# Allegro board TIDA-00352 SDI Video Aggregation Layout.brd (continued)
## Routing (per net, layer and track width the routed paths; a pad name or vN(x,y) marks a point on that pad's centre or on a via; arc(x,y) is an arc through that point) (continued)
GND_CAGE: length 4.8
  L3_SIG2 w1.016: J73.40 J73.39
  vias: v1(20.5,26.95) v1(20.5,26.44) v1(21.01,26.95) v1(21.01,26.44) v1(21.49,26.95) v1(21.49,26.44) v1(26.85,42.01) v1(26.85,41.5) v1(27.33,42.01) v1(27.33,41.5) v1(27.81,42.01) v1(27.81,41.5)
VCC_PRI: length 3
  L3_SIG2 w0.152: v1(11.08,161.18) 11.08,161.61 11.11,161.64 v1(11.11,162.89)
  BOTTOM w0.254: C690.1 9.31,161.06 R776.1
VCC_SEC: length 3
  TOP w0.254: v1(12.55,136) 12.55,135.52 12.51,135.49 v1(12.51,134.29)
  BOTTOM w0.254: R792.1 14.31,136.12 C695.1
VDDA: length 68.9
  TOP w0.254: J100.27 v1(96.59,99.87)
  TOP w1.016: v1(105.92,32.26) 104.27,33.91 C86.1 C85.1 v1(101.35,36.45) v1(101.35,36.96)
  L3_SIG2 w0.152: v1(64.18,98.77) 82.12,98.77 84.52,101.17 91.88,101.17 92.34,100.71 95.75,100.71 v1(96.59,99.87)
  L14_SIG3 w0.152: v1(64.18,73.91) 64.48,74.21 64.48,74.26 64.82,74.6 64.82,77.04 64.18,77.68 v1(64.18,98.77)
  vias: v1(77.22,31.88) v1(97.16,32) v1(100.84,37.47) v1(100.84,36.96) v1(100.84,36.45) v1(101.35,37.47) v1(101.85,37.47) v1(101.85,36.96) v1(101.85,36.45) v1(105.41,32.26) v1(106.43,32.26) v2(41.09,73.16) v2(42.09,74.16) v2(50.09,76.16) v2(50.09,74.16) v2(50.09,73.16) v2(50.09,71.16)
VDDD: length 25.3
  TOP w0.254: J100.31 v1(98.59,99.87)
  TOP w1.016: v1(105.41,87) v1(104.9,87) C109.1 C110.1 102.36,84.07 v1(100.71,82.42)
  L14_SIG3 w0.152: v1(105.92,87.5) 105.92,90.55 100.33,96.14 100.33,98.13 v1(98.59,99.87)
  BOTTOM w0.254: C164.1 46.14,75.16 v2(46.09,75.16)
  vias: v1(52.1,65.32) v1(100.71,82.93) v1(100.71,81.92) v1(104.9,87.5) v1(104.9,86.49) v1(105.41,87.5) v1(105.41,86.49) v1(105.92,87) v1(105.92,86.49) v2(44.09,75.16) v2(44.09,72.16) v2(46.09,73.16) v2(46.09,72.16)
VDDO: length 12.3
  TOP w0.254: v1(83.94,23.17) v1(83.31,23.17) ; J100.35 v1(100.59,99.87)
  TOP w1.016: v1(65.41,133.6) 63.75,135.25 C129.1 C128.1 v1(60.83,137.92) v1(60.83,138.43)
  BOTTOM w0.254: R305.2 v1(32.92,9.14) ; U43.2 v1(25.44,7.87)
  vias: v1(23.51,8.04) v1(24.71,13.26) v1(28,13.26) v1(30.45,73.7) v1(55.54,15.25) v1(55.54,14.61) v1(55.54,13.98) v1(55.69,11.74) v1(55.75,12.83) v1(60.07,13.54) v1(60.33,138.94) v1(60.33,138.43) v1(60.33,137.92) v1(60.83,138.94) v1(61.34,138.94) v1(61.34,138.43) v1(61.34,137.92) v1(64.9,133.6) v1(65.91,133.6) v1(66.17,13.46) v1(67.44,13.46) v1(68.71,13.46) v1(69.98,13.46) v1(74.04,13.46) v1(74.45,102.29) v1(74.45,101.78) v1(74.83,100.89) v1(76,102.12) v1(77.09,103.38) v1(81.66,7.37) v1(82.67,23.17) v1(84.2,7.37) v1(105.66,11.3) v1(106.93,11.3) v1(108.2,11.3) v1(109.47,11.3) v1(110.74,11.3) v1(112.01,11.18) v1(113.28,11.05) v1(114.43,19) v1(115.07,19) v1(115.7,19) v1(118.49,25.53) v1(121.67,18.54) v1(123.06,18.54) v2(45.09,77.16) v2(45.09,70.16)
VDDRA_HS: length 66.4
  TOP w0.254: J100.39 v1(102.59,99.87)
  TOP w1.016: v1(73.03,133.6) 71.37,135.25 C100.1 C99.1 v1(68.45,137.92) v1(68.45,138.43)
  L3_SIG2 w0.152: v1(102.59,99.87) 102.59,102.51 100.08,105.03 95.76,105.03 93.98,106.81 93.98,113.16 91.19,115.95 91.19,130.3 89.92,131.57 75.56,131.57 v1(73.53,133.6)
  vias: v1(67.94,138.94) v1(67.94,138.43) v1(67.94,137.92) v1(68.45,138.94) v1(68.96,138.94) v1(68.96,138.43) v1(68.96,137.92) v1(72.52,133.6) v2(41.09,72.16)
VDDRA_LS: length 9.6
  TOP w0.254: J100.37 v1(101.59,97.28)
  TOP w1.016: v1(97.16,133.73) 95.5,135.38 C90.1 C89.1 v1(92.58,137.92) v1(92.58,138.43)
  vias: v1(92.08,138.94) v1(92.08,138.43) v1(92.08,137.92) v1(92.58,138.94) v1(93.09,138.94) v1(93.09,138.43) v1(93.09,137.92) v1(96.65,133.73) v1(97.66,133.73) v2(49.09,70.16)
VDDRB_HS: length 61.2
  TOP w0.254: J100.43 v1(104.59,99.87)
  TOP w1.016: v1(80.77,133.6) 79.12,135.25 C124.1 C123.1 v1(76.2,137.92) v1(76.2,138.43)
  L3_SIG2 w0.152: v1(104.59,99.87) 104.59,104.58 102.74,106.43 98.42,106.43 95.34,109.51 95.34,114.21 92.25,117.3 92.25,131.41 89.5,134.16 81.84,134.16 v1(81.28,133.6)
  vias: v1(75.69,138.94) v1(75.69,138.43) v1(75.69,137.92) v1(76.2,138.94) v1(76.71,138.94) v1(76.71,138.43) v1(76.71,137.92) v1(80.26,133.6) v2(41.09,76.16)
VDDRB_LS: length 54.8
  TOP w0.254: J100.41 v1(103.59,97.28)
  TOP w1.016: v1(88.77,133.73) 87.12,135.38 C114.1 C113.1 v1(84.2,137.92) v1(84.2,138.43)
  L3_SIG2 w0.152: v1(103.59,97.28) 103.59,102.91 103.05,103.45 103.05,104.47 101.73,105.79 96.9,105.79 95.76,106.93 95.76,108.3 94.49,109.57 94.49,113.68 91.8,116.37 91.8,131.22 v1(89.28,133.73)
  vias: v1(83.69,138.94) v1(83.69,138.43) v1(83.69,137.92) v1(84.2,138.94) v1(84.71,138.94) v1(84.71,138.43) v1(84.71,137.92) v1(88.27,133.73) v2(49.09,77.16)
VDDT: length 60.7
  TOP w0.254: J100.29 v1(97.59,97.28)
  TOP w1.016: v1(118.11,132.46) 116.84,131.19 C95.1 C94.1 v1(113.92,127.89) v1(113.41,127.89)
  L3_SIG2 w0.152: v1(112.9,127.38) 111,127.38 109.22,125.6 109.22,115.32 108.58,114.68 108.58,107.57 110.36,105.79 110.36,104.78 112.05,103.09 112.05,97.09 109.95,95 99.88,95 v1(97.59,97.28)
  vias: v1(64.11,75.06) v1(112.9,128.4) v1(112.9,127.89) v1(113.41,128.4) v1(113.41,127.38) v1(113.92,128.4) v1(113.92,127.38) v1(118.11,132.97) v1(118.11,131.95) v2(43.09,73.16) v2(48.09,74.16) v2(48.09,73.16)
1P0V_A1: length 76
  TOP w0.254: J100.9 v1(87.59,99.87)
  TOP w1.016: v1(101.35,39.65) v1(101.35,40.28) 101.35,43.69 100.33,44.7 91.06,44.7 90.22,43.87 v1(90.22,43.18)
  L14_SIG3 w0.152: v1(87.59,99.87) 90.16,97.3 90.16,68.57 90.6,68.12 90.6,58.88 90.22,58.49 v1(90.22,43.18)
  vias: v1(90.2,42.55) v1(90.2,41.86) v1(90.2,41.22) v1(90.83,42.55) v1(90.83,41.86) v1(90.83,41.22) v1(90.86,43.18) v1(91.21,39.38) v1(100.71,40.31) v1(100.71,39.67) v1(102.03,40.28) v1(102.03,39.65)
1P0V_A1_REG_ADJ: length 0.9
  BOTTOM w0.381: R50.2 v1(93.81,39.38)
1P0V_A1_REG_EN: length 123.4
  TOP w0.254: SW17.1 v1(109.73,132.45)
  L3_SIG2 w0.152: v1(95.25,47.37) 95.94,46.69 95.94,37.01 95.41,36.48 v1(95.41,35.17)
  L14_SIG3 w0.152: v1(95.25,47.37) 95.25,58.44 95.68,58.88 95.68,68.12 95.25,68.56 95.25,81.15 94.36,82.04 94.36,98.3 95.02,98.96 95.02,106.96 95.76,107.7 114.43,107.7 115.75,109.02 115.75,129.24 112.54,132.45 v1(109.73,132.45)
1P0V_A1_REG_SS:
  vias: v1(95.41,37.77)
1P0V_A1_REG_TRIM: length 1
  BOTTOM w0.254: R600.2 95.5,39.39 R52.1
1P0V_A2: length 61.7
  TOP w0.254: J100.11 v1(88.59,97.28)
  L3_SIG2 w0.152: v1(110.01,122.38) 109.83,122.2 109.83,108.61 113.31,105.13 113.31,96.4 110.74,93.83 95.15,93.83 91.26,97.71 90.41,97.71 89.98,97.28 v1(88.59,97.28)
  BOTTOM w1.016: C605.1 110.24,124.08 110.31,124.16 L3.1
  vias: v1(110.03,124.33) v1(110.01,123.7) v1(110.01,123.01) v1(110.64,123.7) v1(110.64,123.01) v1(110.64,122.38) v1(110.67,124.33) v1(111.02,120.53)
1P0V_A2_REG_ADJ: length 0.9
  BOTTOM w0.381: R603.2 v1(113.62,120.53)
1P0V_A2_REG_EN: length 23.4
  TOP w0.254: SW17.3 v1(108.46,132.45)
  L3_SIG2 w0.152: v1(115.22,116.33) 115.82,116.93 115.82,129.16 111.85,133.13 109.14,133.13 v1(108.46,132.45)
1P0V_A2_REG_SS:
  vias: v1(115.22,118.93)
1P0V_A2_REG_TRIM: length 1
  BOTTOM w0.381: R604.1 115.3,121.5 R605.2
1P0V_D1: length 39.4
  TOP w0.254: J100.13 v1(89.59,99.87)
  L3_SIG2 w0.152: v1(89.59,99.87) 87.76,98.04 87.76,95.63 90.93,92.46 107.24,92.46 v1(112.7,87)
  BOTTOM w1.016: C27.1 110.32,87.38 109.94,87 L5.1
  vias: v1(112.67,86.36) v1(112.67,85.67) v1(112.67,85.04) v1(113.33,87) v1(113.31,86.36) v1(113.31,85.67) v1(113.31,85.04) v1(113.69,83.19)
1P0V_D1_REG_ADJ: length 0.9
  BOTTOM w0.381: R67.2 v1(116.29,83.19)
1P0V_D1_REG_EN: length 65.3
  TOP w0.254: SW17.5 v1(107.19,132.45)
  L3_SIG2 w0.152: v1(117.89,78.99) 117.22,79.66 117.22,103.38 117.98,104.14 117.98,104.52 119.51,106.05 119.51,124.94 116.33,128.12 116.33,129.41 112.14,133.6 108.97,133.6 108.95,133.59 108.33,133.59 v1(107.19,132.45)
1P0V_D1_REG_SS:
  vias: v1(117.89,81.59)
1P0V_D1_REG_TRIM: length 1
  BOTTOM w0.381: R601.2 117.97,84.16 R69.1
1P0V_D2: length 77.2
  TOP w0.254: J100.15 v1(90.59,97.28)
  L3_SIG2 w0.152: v1(110.67,92.91) 94.96,92.91 v1(90.59,97.28)
  L14_SIG3 w0.152: v1(110.67,92.91) 110.67,83.01 111.63,82.04 111.63,78.49 111.3,78.16 v1(111.3,43.43)
  BOTTOM w1.016: L7.1 110.95,45.77 110.87,45.69 C613.1
  vias: v1(110.64,42.8) v1(110.64,42.11) v1(110.64,41.48) v1(110.67,43.43) v1(111.28,42.8) v1(111.28,42.11) v1(111.28,41.48) v1(111.66,39.63)
1P0V_D2_REG_ADJ: length 0.9
  BOTTOM w0.381: R607.2 v1(114.26,39.63)
1P0V_D2_REG_EN: length 116.8
  TOP w0.254: SW17.7 v1(105.92,132.45)
  L3_SIG2 w0.152: v1(115.86,35.43) 116.58,35.43 123.27,42.11 123.27,59.61 122.89,59.99 122.89,65.74 123.27,66.12 123.27,76.63 118.87,81.03 118.87,85.98 117.97,86.88 117.97,103.11 120.02,105.16 120.02,125.48 116.84,128.65 116.84,129.67 112.39,134.11 108.2,134.11 108.14,134.05 107.52,134.05 v1(105.92,132.45)
1P0V_D2_REG_SS:
  vias: v1(115.86,38.03)
1P0V_D2_REG_TRIM: length 1
  BOTTOM w0.381: R609.2 115.94,40.6 R608.1
1P5V: length 64.1
  TOP w0.254: J100.17 v1(91.59,99.87)
  L14_SIG3 w0.152: v1(91.59,99.87) 91.59,100.69 89.28,103 89.28,105.66 88.39,106.55 88.39,130.56 87.76,131.19 87.76,144.4 88.14,144.78 88.14,148.21 90.3,150.37 92,150.37 v1(92.96,151.33)
  BOTTOM w1.016: v1(92.33,151.99) 92.33,155.96 91.44,156.84 JMP35.1
  vias: v1(89.16,150.98) v1(91.01,151.99) v1(91.01,151.36) v1(91.64,151.99) v1(91.64,151.36) v1(92.33,151.36) v1(92.96,151.97)
1P5V_REG_EN: length 29.9
  TOP w0.254: SW17.9 v1(104.65,132.45)
  L3_SIG2 w0.152: v1(104.65,132.45) 104.65,134.49 103.81,135.33 103.81,138.24 100.07,141.99 89.15,141.99 84.96,146.18 v1(84.96,146.78)
1P5V_REG_EN_ADJ: length 1
  BOTTOM w0.254: R84.2 v1(89.16,148.29)
1P5V_REG_SS:
  vias: v1(87.56,146.78)
1P5V_REG_TRIM: length 1.4
  BOTTOM w0.254: v1(90.53,146.56) 89.21,146.56 R86.2
1P8_VREG_SS:
  vias: v1(68.51,146.78)
1P8V: length 87.4
  TOP w0.254: J100.19 v1(92.59,97.28)
  L14_SIG3 w0.152: JMP35.3 84.33,156.21 84.33,152.65 82.93,151.25 82.93,133.23 86.36,129.79 86.36,106.93 87.5,105.79 87.5,103.25 89.03,101.73 89.03,99.44 90.75,97.71 90.77,97.71 91.2,97.28 v1(92.59,97.28)
  BOTTOM w1.016: v1(73.28,151.99) 73.28,155.96 76.71,159.38 85.22,159.38 JMP35.3
  vias: v1(70.11,150.98) v1(71.96,151.99) v1(71.96,151.36) v1(72.59,151.99) v1(72.59,151.36) v1(73.28,151.36) v1(73.91,151.97) v1(73.91,151.33)
1P8V_REG_ADJ: length 0.9
  BOTTOM w0.381: R118.2 v1(70.11,148.38)
1P8V_REG_EN: length 47.3
  TOP w0.254: SW17.11 v1(103.38,132.45)
  L3_SIG2 w0.152: v1(103.38,132.45) 103.38,134.37 102.74,135 102.74,138.05 99.44,141.35 87.76,141.35 87,142.11 70.57,142.11 v1(65.91,146.78)
1P8V_REG_TRIM: length 1
  BOTTOM w0.381: R120.1 71.08,146.7 R613.2
2P5V: length 189.2
  TOP w0.254: J100.23 v1(94.59,99.87)
  L3_SIG2 w0.152: v1(14.48,43.56) 14.48,82.17 18.92,86.61 v1(65.28,86.61) ; v1(17.27,43.56) v1(24.51,43.56) ; v1(94.59,99.87) 92.53,99.87 91.69,100.71 84.71,100.71 79.88,95.89 v1(66.17,95.89)
  L14_SIG3 w0.152: v1(65.28,86.61) 66.17,87.5 v1(66.17,95.89) ; v1(37.79,15.3) 37.79,17.97 33.78,21.97 33.78,24.05 28.62,29.21 26.42,29.21 24,31.62 24,43.05 v1(24.51,43.56) ; v1(14.48,43.56) v1(17.27,43.56)
  BOTTOM w0.305: C615.1 37.79,15.3 v1(37.79,15.3)
  BOTTOM w0.635: R616.1 38.67,11.87 v1(37.79,11.87)
  BOTTOM w1.016: JMP77.3 37.72,9.4 37.79,9.46 v1(37.79,11.87) v1(37.79,15.3) U103.5
2P5V_EN: length 3.3
  TOP w0.254: v1(39.68,20.95) 39.08,21.56 39.08,21.76 v1(38.73,22.1)
  BOTTOM w0.254: U103.3 v1(39.68,20.95)
2P5V_LED: length 1.9
  BOTTOM w0.508: R616.2 39.94,11.87 v1(41.78,11.87)
3P3V: length 14
  TOP w0.254: v1(96.72,22.27) 96.88,22.1 U42.27 ; U42.31 v1(96.92,20.1) ; J100.25 v1(95.59,97.28)
  L5_PWR w0.381: 36.84,3.3 JMP77.1 ; JMP77.1 37.72,4.18 ; JMP77.1 37.72,2.43 ; JMP77.1 38.6,3.3 ; JMP62.1 62.99,15.3 ; JMP62.1 62.99,13.55 ; JMP62.1 63.87,14.43 ; JMP62.1 62.12,14.43
  BOTTOM w0.254: v1(93.85,20.32) 94.23,20.32 94.3,20.39 R477.1 ; v1(93.98,22.1) 94.02,22.06 R472.1 ; C298.1 v1(50.49,33.46) ; v1(96.72,22.27) 97.28,22.27 C280.1
  vias: v1(2.16,22.86) v1(7.11,167.96) v1(10.22,167.94) v1(11.55,133.59) v1(12.08,163.59) v1(12.45,167.94) v1(13.53,129.24) v1(13.49,24.64) v1(13.72,21.84) v1(15.11,7.11) v1(16.13,21.34) v1(22.62,20.99) v1(30.51,23.24) v1(32.09,32.73) v1(32.13,31.11) v1(39.68,22.1) v1(44.8,36.37) v1(44.8,26.34) v1(46.7,36.37) v1(46.7,26.34) v1(49.66,39.37) v1(49.78,41.91) v1(50.98,40.13) v1(50.98,39.5) v1(51.74,40.13) v1(51.77,39.5) v1(52.76,40.13) v1(52.76,39.5) v1(53.34,25.81) v1(54.34,20.74) v1(54.36,22.48) v1(54.48,42.67) v1(54.48,41.73) v1(54.48,40.89) v1(54.48,39.5) v1(54.48,38.68) v1(54.48,37.72) v1(73.15,112.14) v1(74.45,103.89) v1(75.13,106.03) v1(75.18,40.51) v1(78.74,107.57) v1(79.12,106.28) v1(79.12,105.27) v1(80.77,111.12) v1(87.12,40.51) v1(88.27,23.17) v1(88.91,23.17) v1(89.54,23.17) v1(94.36,23.5) v1(94.67,21.22) v1(94.67,19.55) v1(96.82,124.33) v1(96.8,123.7) v1(96.8,123.01) v1(96.8,122.38) v1(97.43,123.7) v1(97.43,123.01) v1(97.43,122.38) v1(97.46,124.33) v1(97.82,120.53) v1(108.83,19) v1(109.47,19) v1(110.1,19)
3P3V_C_REG_ADJ: length 0.9
  BOTTOM w0.381: R186.2 v1(66.25,168.79)
3P3V_C_REG_SS:
  vias: v1(67.85,167.19)
3P3V_CLK: length 78
  TOP w0.254: J100.45 v1(105.59,97.28)
  TOP w1.016: 62.87,172.4 C74.1
  L3_SIG2 w0.152: v1(66.67,86.49) 95.63,86.49 98.42,89.28 v1(107.19,89.28)
  L14_SIG3 w0.152: v1(107.19,89.28) 107.19,95.68 v1(105.59,97.28) ; v1(66.67,86.49) 66.67,103.76 62.56,107.88 v1(62.56,110.44)
  vias: v1(31.36,110.97) v1(33.02,111.77) v1(32.96,110.82) v1(45.45,110.72) v1(47.12,111.52) v1(47.06,110.57) v1(55.96,113.76) v1(56.03,112.23) v1(56.24,172.34) v1(56.24,165.74) v1(56.26,173.61) v1(56.26,172.97) v1(56.26,167) v1(56.26,166.37) v1(56.29,139.19) v1(56.29,138.56) v1(56.26,137.92) v1(56.41,160.4) v1(56.41,159.77) v1(56.39,159.13) v1(56.41,153.54) v1(56.41,152.91) v1(56.39,152.27) v1(56.41,146.05) v1(56.41,145.41) v1(56.39,144.78) v1(56.64,130.81) v1(56.67,132.08) v1(56.67,131.44) v1(56.85,173.61) v1(56.85,172.97) v1(56.82,172.34) v1(56.95,167) v1(56.95,166.37) v1(56.92,165.74) v1(56.95,137.92) v1(56.97,139.19) v1(56.97,138.56) v1(57.1,160.4) v1(57.1,159.77) v1(57.07,159.13) v1(57.1,153.54) v1(57.1,152.91) v1(57.07,152.27) v1(57.1,146.05) v1(57.1,145.41) v1(57.07,144.78) v1(57.07,119.36) v1(57.33,130.81) v1(57.35,132.08) v1(57.35,131.44) v1(58.18,119.41) v1(62.64,171.96) v1(62.64,171.27) v1(62.64,170.64) v1(62.61,111.39) v1(62.66,172.59) v1(63.3,172.59) v1(63.27,171.96) v1(63.27,171.27) v1(63.27,170.64) v1(63.65,168.79) v1(73.15,163.58) v1(73.15,161.16) v1(73.28,168.4) v1(73.28,165.99)
3P3V_CLK_REG_EN: length 64.7
  TOP w0.254: SW17.15 v1(100.84,132.45)
  L3_SIG2 w0.152: v1(67.85,164.59) 66.92,164.59 65.48,163.14 65.48,147.01 65.41,146.94 65.41,146.56 65.48,146.49 65.48,146.14 70.01,141.6 86.61,141.6 88.01,140.21 97.66,140.21 100.84,137.03 v1(100.84,132.45)
3P3V_CLK_REG_TRIM: length 1
  BOTTOM w0.381: R610.2 67.93,169.76 R188.1
3P3V_REG_EN: length 17.7
  TOP w0.254: SW17.13 v1(102.11,132.45)
  L3_SIG2 w0.152: v1(102.02,116.33) 102.74,117.05 102.74,130.3 102.11,130.94 v1(102.11,132.45)
3P3V_REG_TRIM: length 1
  BOTTOM w0.254: R171.1 102.09,121.5 R611.2
3P3V_RX:
  vias: v1(36.6,33.93) v1(37.23,33.93) v1(37.87,33.93) v1(46.7,27.86) v1(57.53,39.62) v1(57.53,38.68) v1(57.53,37.85) v1(59.18,37.26) v1(59.31,38.99)
3P3V_TX:
  vias: v1(36.6,34.73) v1(37.23,34.73) v1(37.87,34.73) v1(44.8,27.86) v1(46.7,15.61) v1(52.38,36) v1(57.53,42.67) v1(57.53,41.73) v1(57.53,40.89) v1(59.18,42.98) v1(59.31,41.27)
3P3V_USB: length 5
  TOP w0.254: J101.2 v1(12.98,10.67)
  BOTTOM w0.254: v1(12.98,10.67) 13.41,10.23 R639.2
3P3VREG_ADJ: length 0.9
  BOTTOM w0.254: R169.2 v1(100.42,120.53)
3P3VREG_SS:
  vias: v1(102.02,118.93)
/STATUS1: length 3.7
  BOTTOM w0.254: R708.2 R707.2 21.87,106.54 21.95,106.46 Q106.3
/STATUS1_B: length 1.3
  BOTTOM w0.254: R708.1 U106.6
A4N: length 25.5
  BOTTOM w0.114: C225.1 74.39,72.5 74.39,73.05 71.69,75.76 51.5,75.76 v2(51.09,76.16)
A4P: length 25.5
  BOTTOM w0.114: v2(51.09,75.16) 51.5,75.57 71.61,75.57 72.21,74.96 72.21,74.78 72.44,74.55 72.62,74.55 72.86,74.32 72.86,74.14 73.09,73.9 73.27,73.9 73.5,73.67 73.5,73.49 73.73,73.26 73.92,73.26 74.2,72.97 74.2,72.5 C223.1
A5N: length 38.6
  BOTTOM w0.114: v2(50.09,78.16) 50.09,78.13 50.46,77.75 81.63,77.75 84.54,74.84 84.54,72.51 C221.1
A5P: length 38.6
  BOTTOM w0.114: C219.1 84.35,72.49 84.35,72.73 84.16,72.93 84.16,73.19 84.35,73.38 84.35,73.65 84.16,73.84 84.16,74.1 84.35,74.3 84.35,74.76 81.55,77.56 50.46,77.56 50.09,77.2 v2(50.09,77.16)
A6N: length 53
  BOTTOM w0.114: v2(51.09,79.16) 51.5,78.76 95.61,78.76 99.79,74.58 99.79,72.5 C217.1
A6P: length 53.1
  BOTTOM w0.114: C215.1 99.6,72.5 99.6,74.5 99.43,74.67 99.24,74.67 99.01,74.9 99.01,75.09 98.78,75.32 98.6,75.32 98.37,75.55 98.37,75.74 98.13,75.97 97.95,75.97 97.72,76.2 97.72,76.38 95.54,78.57 51.5,78.57 v2(51.09,78.16)
A7N: length 67.5
  BOTTOM w0.114: C213.1 109.95,72.5 109.95,74.33 103.8,80.47 48.81,80.47 48.5,80.17 48.5,79.68 48.5,79.56 v2(48.09,79.16)
A7P: length 67.5
  BOTTOM w0.114: v2(49.09,79.16) 48.69,79.56 48.69,79.57 48.69,80.09 48.89,80.28 103.72,80.28 107.14,76.86 107.14,76.79 107.14,76.6 107.33,76.41 107.41,76.41 107.6,76.41 107.79,76.22 107.79,76.14 107.79,75.95 107.98,75.76 108.06,75.76 108.25,75.76 108.44,75.57 108.44,75.49 108.44,75.3 108.63,75.11 108.7,75.11 108.89,75.11 109.08,74.92 109.08,74.85 109.08,74.66 109.27,74.47 109.35,74.47 109.54,74.47 109.76,74.25 109.76,72.5 C211.1
AMUXA: length 123.7
  L3_SIG2 w0.152: JMP48.7 91.57,3.43 78.87,3.43 78.05,4.24 78.05,27.51 78.23,27.69 v1(78.23,30.73) 78.23,31.24 79.76,32.77 79.76,34.42 81,35.66 83.53,35.66 88.01,40.14 88.01,45.45 78.73,54.74 62.48,54.74 56.52,60.71 46.86,60.71 40.39,67.18 40.39,69.46 v2(41.09,70.16)
  BOTTOM w0.114: R256.1 v1(78.23,30.73)
AMUXB: length 111.4
  L3_SIG2 w0.152: v2(48.09,71.16) 48.09,70.75 46.09,68.75 44.04,68.75 43.63,68.35 43.63,67.24 47.62,63.25 56.73,63.25 63.72,56.26 81.66,56.26 94.11,43.81 94.11,41.15 94.41,40.84 94.41,33.45 94.84,33.02 95.43,33.02 97.16,31.29 v1(97.16,30.86) 97.16,28.07 93.42,24.33 93.42,20.14 93.47,20.09 93.47,11.05 91.19,8.76 91.19,6.49 90.55,5.85 JMP48.9
  BOTTOM w0.114: R263.1 v1(97.16,30.86)
CHA_CLKOUTN_CONNECTOR: length 93
  BOTTOM w0.114: C196.2 43.36,64.59 43.53,64.42 43.53,63.27 53.21,53.59 53.21,45.85 54.61,44.45 74.55,44.45 75.31,45.21 105.41,45.21 115.06,54.86 115.06,57.28 v1(115.57,57.78)
CHA_CLKOUTP_CONNECTOR: length 93
  BOTTOM w0.114: C194.2 43.9,64.59 43.72,64.42 43.72,63.35 53.4,53.67 53.4,45.93 54.69,44.64 74.47,44.64 75.23,45.4 105.33,45.4 112.14,52.21 112.14,52.55 112.48,52.9 112.82,52.9 113.01,53.08 113.01,53.48 113.26,53.72 113.4,53.72 113.58,53.72 113.79,53.93 113.79,54.23 114.05,54.48 114.41,54.48 114.87,54.94 114.87,57.21 v1(114.3,57.78)
CHB_CLKOUTN_CONNECTOR: length 208.8
  BOTTOM w0.114: C204.2 39.15,64.02 39.32,63.85 39.32,61.8 37.72,60.2 34.02,60.2 33.86,60.2 29.75,56.09 29.75,47.29 28.99,46.53 28.88,46.42 21.54,46.42 20.13,47.83 20.13,83.88 17.14,86.87 17.14,96.14 23.62,102.62 57.53,102.62 62.48,97.66 62.48,84.82 66.22,81.09 104.56,81.09 106,79.65 106,79.42 106,79.27 106.27,78.99 106.55,78.99 106.82,78.73 106.82,78.47 106.93,78.36 107.23,78.36 107.3,78.36 107.52,78.14 107.52,78.02 107.52,77.9 107.69,77.73 107.81,77.73 107.93,77.73 108.1,77.56 108.1,77.44 108.1,77.32 108.27,77.15 108.39,77.15 108.5,77.15 108.68,76.98 108.68,76.86 108.68,76.74 108.85,76.57 108.97,76.57 109.08,76.57 109.25,76.4 109.25,76.28 109.26,76.17 109.43,76 109.54,76 109.66,76 109.83,75.82 109.83,75.71 109.83,75.59 110,75.42 110.12,75.42 110.24,75.42 110.41,75.25 110.41,75.13 110.41,75.01 110.58,74.84 110.7,74.84 110.82,74.84 110.99,74.67 110.99,74.55 110.99,74.43 111.16,74.26 111.28,74.26 111.4,74.26 111.76,73.9 111.76,72.26 112.39,71.63 114.3,71.63 114.81,71.12 114.81,69.72 v1(114.3,69.22)
CHB_CLKOUTP_CONNECTOR: length 208.7
  BOTTOM w0.114: v1(115.57,69.22) 115,69.79 115,71.2 114.38,71.82 112.47,71.82 111.95,72.34 111.95,73.98 104.65,81.28 66.29,81.28 62.67,84.9 62.67,97.74 57.61,102.81 23.54,102.81 16.95,96.22 16.95,86.79 19.94,83.8 19.94,47.75 21.46,46.23 28.96,46.23 29.07,46.34 29.94,47.21 29.94,56.01 33.94,60.01 37.8,60.01 39.51,61.72 39.51,63.85 39.69,64.02 C202.2
CLK_/RST: length 7.8
  TOP w0.254: v1(35.36,110.82) 36.32,110.82 36.83,110.31 36.83,107.92 v1(38.47,106.28)
  BOTTOM w0.254: v1(35.36,110.82) 36.75,110.82 R744.2
CLK_/RST_B: length 1.3
  BOTTOM w0.254: U113.6 R746.1
CLK_DVDD: length 88.6
  TOP w0.254: J100.57 v1(111.59,97.28) ; U100.48 15.41,147.78 v1(15.11,148.08)
  TOP w0.508: v1(54.46,130.81) C627.1
  TOP w1.016: v1(21.3,105.4) v1(21.3,109.59)
  L3_SIG2 w0.152: v1(111.59,97.28) 109.76,95.45 100.64,95.45 98.7,97.39 98.7,99.06 96.13,101.63 93.7,101.63 91.31,104.01 91.31,104.36 90.93,104.74 90.93,112.52 85.47,117.98 65.15,117.98 57.4,125.73 57.4,128.47 v1(55.07,130.81)
  BOTTOM w0.254: C643.1 15.11,147.25 v1(15.11,148.08)
  vias: v1(8.27,129.45) v1(10.41,119.16) v1(11.43,148.53) v1(12.32,117.73) v1(12.33,115.23) v1(12.7,148.53) v1(14.99,156.58) v1(16.38,157.1) v1(17.65,156.58) v1(18.8,157.1) v1(54.48,132.08) v1(54.48,131.44) v1(55.12,132.08) v1(55.12,131.44)
CLK_RST: length 8
  TOP w0.254: v1(35.36,112.72) 36.7,112.72 37.53,111.89 37.53,109.12 v1(38.47,108.18)
  BOTTOM w0.254: R745.2 36.74,112.72 v1(35.36,112.72)
CLK_RST_B: length 1.3
  BOTTOM w0.254: R747.1 U113.4
CLK_RST_PB: length 6.4
  TOP w0.254: v1(32.96,112.72) 32.96,113.28 32.34,113.9 SW15.1
  BOTTOM w0.254: v1(32.96,112.72) 31.43,112.72 R742.1 R743.1
CLK_SPI_CLK/PIN4: length 28.6
  TOP w0.254: U100.5 v1(15.58,144)
  L3_SIG2 w0.152: v1(10.41,120.31) 11.05,120.94 11.05,136.14 12.06,137.16 12.06,137.67 15.15,140.75 15.15,143.57 v1(15.58,144)
  L14_SIG3 w0.152: v1(10.41,120.31) 9.55,121.17 9.55,121.33 v1(9.24,121.64)
CLK_SPI_LE/PIN3: length 31.5
  TOP w0.254: v1(12.57,144.48) 13.06,144.48 13.08,144.5 U100.4
  L3_SIG2 w0.152: v1(8.26,127.46) 7.84,127.89 7.84,139.74 v1(12.57,144.48)
  L14_SIG3 w0.152: v1(9.31,119.16) 7.49,120.98 7.49,125.35 8.26,126.12 v1(8.26,127.46)
  BOTTOM w0.254: R758.2 R752.2
CLK_SPI_MISO/PIN2: length 31.9
  TOP w0.254: U100.3 v1(15.58,145)
  L3_SIG2 w0.152: v1(15.58,145) 14.69,144.11 14.69,141.7 10.16,137.17 10.16,134.87 9.53,134.24 9.53,125.86 9.91,125.48 9.91,118.12 v1(10.3,117.73)
  BOTTOM w0.254: R751.2 v1(10.3,117.73)
CLK_SPI_MOSI/PIN1: length 35.1
  TOP w0.254: U100.2 v1(13.72,145.5)
  L3_SIG2 w0.152: v1(13.72,145.5) 14.18,145.05 14.18,142.07 8.81,136.7 8.81,116.71 v1(10.3,115.23)
  BOTTOM w0.254: R750.2 v1(10.3,115.23)
CLK_VCC: length 118.3
  TOP w0.254: R685.1 v1(20.6,163.15) ; C628.1 v1(54.2,144.78) ; R684.1 v1(20.6,164.77) ; J100.59 v1(112.59,99.87) ; R690.1 v1(24.46,169.14) ; U105.5 23.51,164.71 v1(23.37,164.85) 22.81,165.4 C670.1 C654.1 22.81,167.53 22.95,167.67 R688.1 ; R689.1 v1(26.09,169.14)
  TOP w0.508: v1(54.2,144.78) C629.1
  L3_SIG2 w0.152: v1(112.59,99.87) 112.59,96.58 110.29,94.28 98.67,94.28 97.05,95.91 97.05,100.06 95.94,101.17 92.63,101.17 90.04,103.76 90.04,112.65 85.22,117.47 64.9,117.47 53.64,128.73 53.64,143.54 v1(54.89,144.78)
  BOTTOM w0.254: R665.1 v1(24.51,135.88) ; U104.5 24.57,132.97 v1(24.43,133.11) 23.87,133.67 C655.1 C669.1 21.75,133.67 21.61,133.52 R669.1 ; R670.1 v1(20.14,130.39) ; R666.1 v1(26.13,135.88) ; R671.1 v1(20.14,132.02)
  vias: v1(54.23,146.05) v1(54.23,145.41) v1(54.86,146.05) v1(54.86,145.41)
CLK_VDD_IN: length 97.1
  TOP w0.254: C624.1 v1(54.08,137.92) ; U100.7 15.11,143 15.11,143 v1(15.58,143) ; U100.10 v1(15.58,141.5) ; J100.55 v1(110.59,99.87)
  TOP w0.508: v1(54.08,137.92) C625.1
  L3_SIG2 w0.152: v1(110.59,99.87) 110.59,96.99 109.51,95.91 101.7,95.91 99.31,98.3 99.31,100.46 97.69,102.08 94.01,102.08 92.08,104.01 92.08,112.27 85.85,118.49 65.41,118.49 57.91,125.98 57.91,133.73 57.28,134.37 54.76,136.88 v1(54.76,137.92)
  BOTTOM w0.254: v1(15.58,143) 14.7,143 C641.1 ; v1(15.58,141.5) 14.54,140.46 R778.2
  vias: v1(54.1,139.19) v1(54.1,138.56) v1(54.74,139.19) v1(54.74,138.56)
CLK_VDD_OUTA: length 120.1
  TOP w0.254: 18.4,140.72 v1(20.42,140.72) ; 18.4,140.72 17.91,140.23 U100.18 ; 18.4,140.72 15.75,140.72 15.48,140.44 15.48,140.34 15.41,140.28 U100.13 ; U100.30 21.04,143 20.7,142.66 v1(20.7,142.11) ; U100.27 v1(20.75,141.5) ; C620.1 v1(54.08,152.27) ; J100.51 v1(108.59,99.87)
  TOP w0.508: v1(54.08,152.27) C621.1
  L3_SIG2 w0.152: v1(54.76,152.27) 54.76,151.49 57.78,148.46 57.78,134.51 58.42,133.87 58.42,126.24 65.66,119 86.36,119 92.96,112.39 92.96,104.9 95.25,102.62 98.93,102.62 100.08,101.47 100.08,98.19 101.89,96.37 109.32,96.37 110.05,97.09 110.05,98.42 v1(108.59,99.87)
  BOTTOM w0.254: v1(54.76,152.27) L102.2 v1(54.08,152.27) ; v1(20.75,141.5) 21.26,140.99 C645.1 21.24,140.72 v1(20.42,140.72) ; C644.1 19.83,140.12 v1(20.42,140.72) ; v1(20.42,140.72) 20.97,140.17 C647.1 ; v1(20.7,142.11) 21.28,142.11 C646.1
  vias: v1(54.1,153.54) v1(54.1,152.91) v1(54.74,153.54) v1(54.74,152.91)
CLK_VDD_OUTB: length 118.1
  TOP w0.254: J100.53 v1(109.59,97.28) ; U100.34 21.05,145 20.7,144.65 v1(20.7,144.48) ; C622.1 v1(54.08,159.13) ; v1(19.08,138.3) 20.3,138.3 20.91,138.91 U100.24 ; U100.19 v1(18.41,138.81) ; U100.31 21.09,143.5 v1(20.7,143.89)
  TOP w0.508: v1(54.08,159.13) C623.1
  L3_SIG2 w0.152: v1(54.76,159.13) 58.93,154.97 58.93,126.49 65.91,119.51 86.74,119.51 93.47,112.78 93.47,105.54 95.38,103.63 99.82,103.63 101.47,101.98 101.47,98.75 103.4,96.82 107.87,96.82 108.33,97.28 v1(109.59,97.28)
  BOTTOM w0.254: C650.1 18.87,139.62 19.08,139.42 v1(19.08,138.3) ; C649.1 17.51,139.12 17.81,138.81 v1(18.41,138.81) ; v1(20.7,144.48) 20.85,144.48 21.04,144.67 C648.1 ; v1(20.7,143.89) 21.07,143.53 C651.1
  vias: v1(54.1,160.4) v1(54.1,159.77) v1(54.74,160.4) v1(54.74,159.77)
CLK_VDD_PLL: length 107.4
  TOP w0.254: J100.47 v1(106.59,99.87) ; U100.37 22.05,146.77 v1(22.48,147.19) ; C616.1 v1(54.08,165.74)
  TOP w0.508: v1(54.08,165.74) 52.58,165.74
  L3_SIG2 w0.152: v1(54.76,165.74) 59.54,160.96 59.54,145.72 70.64,134.62 89.69,134.62 92.71,131.6 92.71,121.28 96.32,117.68 96.32,114.35 96.16,114.2 96.16,110.05 98.77,107.44 103.1,107.44 106.59,103.95 v1(106.59,99.87)
  BOTTOM w0.254: v1(22.48,147.19) 21.28,147.19 C638.1
  vias: v1(54.1,167) v1(54.1,166.37) v1(54.74,167) v1(54.74,166.37)
CLK_VDD_PLL_A: length 163.9
  TOP w0.254: v1(21.21,147.96) 20.73,147.96 20.41,147.64 U100.38 ; U100.39 19.91,147.95 20.68,148.72 v1(21.21,148.72) ; J100.49 v1(107.59,97.28) ; C618.1 v1(54.08,172.34)
  TOP w0.508: v1(54.08,172.34) C619.1
  L3_SIG2 w0.152: v1(107.59,97.28) 107.59,100.95 108.02,101.39 108.02,104.7 104.78,107.95 98.91,107.95 96.62,110.23 96.62,113.89 96.77,114.05 96.77,118.49 93.6,121.67 93.6,133.45 85.95,141.1 69.3,141.1 63.37,147.02 63.37,156.21 60.83,158.75 60.83,160.66 58.67,162.81 58.67,165.89 56.74,167.82 32.31,167.82 30.86,166.37 30.86,157.61 v1(21.21,147.96)
  BOTTOM w0.254: v1(21.21,148.72) 20.41,148.72 C640.1 C639.1
  vias: v1(54.1,173.61) v1(54.1,172.97) v1(54.74,173.61) v1(54.74,172.97) v1(54.76,172.34)
CLKA0N: length 4.3
  BOTTOM w0.114: U104.10 27.37,130.94 27.53,131.1 27.99,131.1 28.57,131.68 28.99,131.68 29.09,131.58 R677.1 30.27,131.58 30.41,131.44 C660.2
CLKA0N_CON: length 36
  BOTTOM w0.114: v1(38.23,161.04) 37.72,161.54 34.04,161.54 32.64,160.15 32.64,132.08 32.23,131.67 31.83,131.67 31.61,131.44 C660.1
CLKA0P: length 4.3
  BOTTOM w0.114: 26.8,131.44 27.37,131.44 27.53,131.29 27.91,131.29 28.49,131.87 28.99,131.87 29.09,131.96 R676.1 30.29,131.96 30.41,132.08 C659.1
CLKA0P_CON: length 36.1
  BOTTOM w0.114: C659.2 31.61,132.08 31.83,131.86 32.15,131.86 32.45,132.16 32.45,160.23 33.96,161.73 37.66,161.73 v1(38.23,162.31)
CLKA1N: length 4.2
  BOTTOM w0.114: U104.12 27.37,129.94 27.53,130.1 27.93,130.1 28.26,129.77 28.99,129.77 29.09,129.68 R679.1 30.27,129.68 30.41,129.54 C662.2
CLKA1N_CON: length 27.6
  BOTTOM w0.114: C662.1 31.61,129.54 31.83,129.76 32.5,129.76 33.53,130.79 33.53,150.35 34.5,151.32 37.78,151.32 v1(38.23,150.88)
CLKA1N_IN_CON: length 73.9
  BOTTOM w0.114: v1(49.66,167.39) 50.16,166.88 51.18,166.88 51.94,167.64 51.94,170.43 50.61,171.77 32.58,171.77 29.21,168.4 29.21,152.16 29.21,152 23.3,146.1 23.3,139.37 17.53,133.59 17.53,131.95 18.16,131.32 18.41,131.32 18.55,131.46 R675.1 C658.2
CLKA1P: length 4.2
  BOTTOM w0.114: U104.11 27.37,130.45 27.53,130.29 28.01,130.29 28.34,129.96 28.99,129.96 29.09,130.06 R678.1 30.29,130.06 30.41,130.18 C661.1
CLKA1P_CON: length 27.7
  BOTTOM w0.114: v1(38.23,152.15) 37.59,151.51 34.42,151.51 33.34,150.43 33.34,130.87 32.42,129.95 31.83,129.95 31.61,130.18 C661.2
CLKA1P_IN_CON: length 75.2
  BOTTOM w0.114: C657.2 R674.1 18.59,130.95 18.41,131.13 18.08,131.13 17.34,131.87 17.34,133.67 23.11,139.45 23.11,146.18 29.02,152.08 29.02,168.48 32.5,171.96 32.65,171.96 50.69,171.96 52.13,170.51 52.13,167.56 51.26,166.69 50.23,166.69 v1(49.66,166.12)
CLKA2N: length 4.2
  BOTTOM w0.114: C664.2 26.04,125.73 26.21,125.9 R681.1 26.21,127.05 26.31,127.15 26.31,127.42 25.73,128 25.73,128.49 25.57,128.64 U104.14
CLKA2N_CON: length 23.2
  BOTTOM w0.114: v1(38.23,135.64) 37.72,136.14 34.8,136.14 34.29,135.64 34.29,128.02 29.72,123.44 26.54,123.44 26.26,123.73 26.26,124.31 26.04,124.53 C664.1
CLKA2P: length 4.2
  BOTTOM w0.114: C663.1 26.67,125.73 26.59,125.8 R680.1 26.59,127.05 26.5,127.15 26.5,127.5 25.92,128.08 25.92,128.49 26.07,128.64 U104.13
CLKA2P_CON: length 22.9
  BOTTOM w0.114: v1(38.23,136.91) 37.66,136.33 34.72,136.33 34.1,135.71 34.1,128.09 29.64,123.63 26.62,123.63 26.45,123.81 26.45,124.31 26.67,124.53 C663.2
CLKA3N: length 4.1
  BOTTOM w0.114: U104.16 24.57,128.64 24.73,128.49 24.73,127.96 24.4,127.63 24.4,127.15 24.31,127.05 R683.1 24.31,125.9 24.13,125.73 C666.2
CLKA3N_CON: length 18.4
  BOTTOM w0.114: C666.1 24.13,124.53 24.35,124.31 24.35,122.59 25.02,121.92 30.1,121.92 34.16,125.98 37.72,125.98 v1(38.23,125.48)
CLKA3P: length 4.1
  BOTTOM w0.114: U104.15 25.07,128.64 24.92,128.49 24.92,127.88 24.59,127.55 24.59,127.15 24.69,127.05 R682.1 24.69,125.8 24.77,125.73 C665.1
CLKA3P_CON: length 18.1
  BOTTOM w0.114: v1(38.23,126.75) 37.66,126.17 34.08,126.17 30.02,122.11 25.1,122.11 24.54,122.67 24.54,124.31 24.77,124.53 C665.2
CLKA_IN_N0: length 4.1
  BOTTOM w0.114: C653.1 25.57,136.15 R666.2 R668.2 25.57,134.43 25.41,134.27 25.41,134.16 25.42,134.15 25.42,132.9 25.57,132.75 U104.7
CLKA_IN_N1: length 3.9
  BOTTOM w0.114: 23.85,131.44 23.27,131.44 23.12,131.29 21.9,131.29 21.89,131.3 21.69,131.3 21.54,131.46 R673.1 R671.2 C658.1
CLKA_IN_N_Y5N: length 13.3
  TOP w0.114: U100.29 22.4,142.5 22.55,142.35 24.66,142.35 24.91,142.1 25.74,142.1 v1(26.05,142.41)
  BOTTOM w0.114: C653.2 25.58,137.02 25.42,137.18 25.42,138.18 25.86,138.62 27,138.62 27.75,139.37 27.75,141.68 27.34,142.1 26.37,142.1 v1(26.05,142.41)
CLKA_IN_P0: length 4.1
  BOTTOM w0.114: U104.6 25.07,132.75 25.23,132.9 25.23,134.08 25.22,134.08 25.22,134.27 25.06,134.43 R667.2 R665.2 25.06,136.15 C652.1
CLKA_IN_P1: length 3.9
  BOTTOM w0.114: U104.3 23.27,130.94 23.12,131.1 21.82,131.1 21.81,131.11 21.69,131.11 21.54,130.95 R672.1 R670.2 C657.1
CLKA_IN_P_Y5P: length 13
  TOP w0.114: v1(26.05,141.59) 25.74,141.9 24.83,141.9 24.58,142.16 22.55,142.16 22.4,142 U100.28
  BOTTOM w0.114: v1(26.05,141.59) 26.37,141.9 27.26,141.9 27.56,141.6 27.56,139.45 26.92,138.81 25.78,138.81 25.23,138.26 25.23,137.18 25.07,137.02 C652.2
CLKA_IN_SEL: length 26.8
  TOP w0.254: SW18.1 30.22,120.28 27.81,122.68 24.77,122.68 21.64,125.81 v1(21.64,128.79) 20.95,129.47 v1(20.95,135.76)
  BOTTOM w0.254: v1(21.64,128.79) 21.64,129.42 22.66,130.45 U104.2 ; R669.2 v1(20.95,135.76)
CLKB0N: length 4.5
  TOP w0.114: C675.2 25.02,158.67 24.89,158.79 R696.1 24.89,160.19 24.8,160.29 24.8,160.71 25.38,161.29 25.38,161.75 25.53,161.91 U105.10
CLKB0N_CON: length 35.3
  TOP w0.114: J102.A7 37.69,131.29 33.19,131.29 31.94,132.54 31.94,136.86 28.51,140.29 28.51,149.94 24.8,153.65 24.8,157.24 25.02,157.47 C675.1
CLKB0P: length 4.5
  TOP w0.114: C674.1 24.38,158.67 24.51,158.79 R695.1 24.51,160.19 24.61,160.29 24.61,160.79 25.19,161.37 25.19,161.75 25.03,161.91 U105.9
CLKB0P_CON: length 35.6
  TOP w0.114: J102.A6 37.69,131.1 33.12,131.1 31.75,132.46 31.75,136.78 28.32,140.21 28.32,149.86 24.61,153.57 24.61,157.24 24.38,157.47 C674.2
CLKB1N: length 4.4
  TOP w0.114: C677.2 26.92,158.67 26.8,158.79 R698.1 26.8,160.19 26.7,160.29 26.7,161.02 26.38,161.35 26.38,161.75 26.53,161.91 U105.12
CLKB1N_CON: length 24.4
  TOP w0.114: C677.1 26.92,157.47 26.7,157.24 26.7,154.67 30.42,150.95 30.42,144.22 33.19,141.45 37.69,141.45 J102.A15
CLKB1N_IN_CON: length 18.3
  TOP w0.114: J102.A35 37.69,166.85 32.67,166.85 30.99,168.53 30.99,170.05 28.96,172.09 25.91,172.09 25.18,171.35 25.18,170.62 25.02,170.46 R694.1 C673.2
CLKB1P: length 4.4
  TOP w0.114: U105.11 26.03,161.91 26.19,161.75 26.19,161.27 26.51,160.94 26.51,160.29 26.42,160.19 R697.1 26.42,158.79 26.29,158.67 C676.1
CLKB1P_CON: length 24.7
  TOP w0.114: J102.A14 37.69,141.26 33.12,141.26 30.23,144.15 30.23,150.88 26.51,154.59 26.51,157.24 26.29,157.47 C676.2
CLKB1P_IN_CON: length 18
  TOP w0.114: J102.A34 37.69,166.66 32.59,166.66 30.8,168.45 30.8,169.97 28.88,171.89 25.99,171.89 25.37,171.28 25.37,170.62 25.53,170.46 R693.1 C672.2
CLKB2N: length 4.1
  TOP w0.114: C679.2 30.59,163.19 30.46,163.07 R700.1 29.42,163.07 29.33,162.97 29.05,162.97 28.47,163.55 27.99,163.55 27.83,163.71 U105.14
CLKB2N_CON: length 22.5
  TOP w0.114: C679.1 31.78,163.19 32.01,162.97 32.5,162.97 33.08,162.38 33.08,147.78 34.37,146.49 37.66,146.49 J102.A19
CLKB2P: length 4.1
  TOP w0.114: C678.1 30.59,162.56 30.46,162.69 R699.1 29.42,162.69 29.33,162.78 28.97,162.78 28.39,163.36 27.99,163.36 27.83,163.21 U105.13
CLKB2P_CON: length 22.4
  TOP w0.114: J102.A18 37.72,146.3 34.29,146.3 32.89,147.7 32.89,162.31 32.42,162.78 32.01,162.78 31.78,162.56 C678.2
CLKB3N: length 4
  TOP w0.114: U105.16 27.83,164.71 27.99,164.55 28.52,164.55 28.85,164.88 29.33,164.88 29.42,164.97 R702.1 30.46,164.97 30.59,165.1 C681.2
CLKB3N_CON: length 14.5
  TOP w0.114: C681.1 31.78,165.1 32.01,164.88 33.26,164.88 33.85,164.29 33.85,157.3 34.37,156.78 37.78,156.78 J102.A27
CLKB3P: length 4
  TOP w0.114: C680.1 30.59,164.47 30.46,164.59 R701.1 29.42,164.59 29.33,164.69 28.92,164.69 28.6,164.36 27.99,164.36 27.83,164.21 U105.15
CLKB3P_CON: length 14.5
  TOP w0.114: J102.A26 37.59,156.59 34.29,156.59 33.66,157.23 33.66,164.21 33.18,164.69 32.01,164.69 31.78,164.47 C680.2
CLKB_IN_N0: length 4.1
  TOP w0.114: C668.1 20.32,163.71 R685.2 21.09,163.7 R687.1 21.99,163.7 22.15,163.86 23.58,163.86 23.73,163.71 U105.7
CLKB_IN_N1: length 3.9
  TOP w0.114: C673.1 R690.2 R692.1 25.02,167.74 25.18,167.58 25.18,167.39 25.19,167.38 25.19,166.16 25.03,166.01 U105.4
CLKB_IN_N_Y7N: length 26.3
  TOP w0.114: C668.2 19.46,163.7 19.3,163.86 18.32,163.86 18.16,163.7 18.16,161.42 22.73,156.84 22.73,153.29 25.65,150.37 25.65,146.8 24.52,145.66 22.55,145.66 22.4,145.5 U100.35
CLKB_IN_P0: length 4.1
  TOP w0.114: C667.1 20.32,164.22 R684.2 21.09,164.21 R686.1 21.99,164.21 22.15,164.05 23.58,164.05 23.73,164.21 U105.6
CLKB_IN_P1: length 3.9
  TOP w0.114: U105.3 25.53,166.01 25.38,166.16 25.38,167.46 25.37,167.47 25.37,167.58 25.53,167.74 R691.1 C672.1
CLKB_IN_P_Y7P: length 26.3
  TOP w0.114: U100.36 22.4,146 22.55,145.85 24.44,145.85 25.46,146.88 25.46,150.29 22.54,153.21 22.54,156.77 17.97,161.34 17.97,163.78 18.24,164.05 19.3,164.05 19.46,164.21 C667.2
CLKB_IN_SEL: length 71.7
  TOP w0.152: v1(20.84,168.32) R688.2
  TOP w0.254: v1(27.69,167.64) 27.05,167.64 26.03,166.62 U105.2 ; SW18.3 v1(27.05,117.47)
  L3_SIG2 w0.152: v1(27.05,117.47) 27.05,123.83 23.88,127 23.88,135.76 18.36,141.27 18.36,146.23 17.02,147.57 17.02,148.59 18.08,149.66 18.08,156.76 18.03,156.81 18.03,166.75 19.61,168.32 v1(20.84,168.32)
  BOTTOM w0.254: v1(20.84,168.32) 20.93,168.24 27.09,168.24 v1(27.69,167.64)
CLKOUTAN: length 5.6
  BOTTOM w0.114: 43.36,65.45 C196.1 43.36,65.46 43.51,65.61 43.51,67.98 43.51,67.99 43.51,68.33 43.48,68.37 43.27,68.58 43.2,68.58 43.2,68.58 42.85,68.58 42.5,68.93 42.5,69.75 42.5,69.75 v2(42.09,70.16)
CLKOUTAN_SMA: length 21.2
  BOTTOM w0.152: v1(48.19,52.03) 48.19,55.21 47.74,55.66 46.44,55.66 arc(45.94,55.87) 45.73,56.37 45.73,56.82 arc(45.02,57.54) 44.31,56.82 44.31,56.37 arc(44.1,55.87) 43.59,55.66 43.18,55.66 42.39,56.45 42.39,65.05 C198.2
CLKOUTAP: length 5.6
  BOTTOM w0.114: 43.9,65.45 C192.1 43.9,65.46 43.7,65.66 43.7,67.9 43.7,67.91 43.7,68.35 43.7,68.41 43.67,68.44 43.67,68.45 43.43,68.68 43.35,68.77 43.28,68.77 43.28,68.77 42.93,68.77 42.69,69 42.69,69.76 v2(43.09,70.16)
CLKOUTAP_SMA: length 21.2
  BOTTOM w0.152: v1(58.35,52.03) 58.35,55.01 56.52,56.85 54.38,56.85 51.61,59.61 50.3,59.61 C192.2
CLKOUTBN: length 5.6
  BOTTOM w0.114: v2(42.09,68.16) 42.5,67.76 42.5,67.64 42.5,67.49 41.96,66.95 40.68,66.95 39.32,65.59 39.32,65.06 C206.1
CLKOUTBN_SMA: length 21.2
  BOTTOM w0.152: C206.2 37.35,63.65 31.09,63.65 30.38,62.95 arc(29.88,62.74) 29.38,62.95 29.35,62.98 arc(28.34,62.98) 28.34,61.97 28.37,61.94 arc(28.58,61.44) 28.37,60.94 25.33,57.89 v1(25.33,54.57)
CLKOUTBP: length 5.6
  BOTTOM w0.114: C200.1 39.51,65.06 39.51,65.52 40.76,66.76 42.04,66.76 42.69,67.41 42.69,67.64 42.69,67.76 v2(43.09,68.16)
CLKOUTBP_SMA: length 21.2
  BOTTOM w0.152: C200.2 41.3,63.83 41.3,59.51 arc(41.09,59.01) 40.59,58.8 40.2,58.8 arc(39.93,58.75) 39.7,58.59 39.02,57.92 arc(38.81,57.41) 39.02,56.91 40.22,55.71 arc(40.22,54.71) 39.21,54.71 38.01,55.91 arc(37.51,56.11) 37.01,55.91 35.49,54.39 v1(35.49,52.03)
D12_1:
  vias: v1(79.63,22.44)
D12_2:
  vias: v1(79.63,24.54)
D13_1:
  vias: v1(75.69,22.48)
D13_2:
  vias: v1(75.69,24.56)
D14_1:
  vias: v1(67.82,22.48)
D14_2:
  vias: v1(67.82,24.54)
D15_1:
  vias: v1(63.88,22.44)
D15_2:
  vias: v1(63.88,24.56)
D16_1:
  vias: v1(71.75,22.44)
D16_2:
  vias: v1(71.75,24.56)
D101_1:
  vias: v1(24.04,112.62)
D101_2: length 1.3
  BOTTOM w0.254: R705.1 v1(21.94,112.62)
D102_1:
  vias: v1(15.65,106.54)
D102_2:
  vias: v1(13.55,106.54)
D103_1:
  vias: v1(15.65,108.44)
D103_2:
  vias: v1(13.55,108.44)
D104_1:
  vias: v1(63.45,105.9)
D104_2:
  vias: v1(61.35,105.9)
D105_1:
  vias: v1(63.45,107.8)
D105_2:
  vias: v1(61.35,107.8)
D106_1:
  vias: v1(47.95,106.03)
D106_2:
  vias: v1(45.85,106.03)
D107_1:
  vias: v1(47.95,107.93)
D107_2:
  vias: v1(45.85,107.93)
D108_1:
  vias: v1(33.86,106.28)
D108_2:
  vias: v1(31.75,106.28)
D109_1:
  vias: v1(33.86,108.18)
D109_2:
  vias: v1(31.75,108.18)
DISABLE_SFP+_TX: length 6.7
  L3_SIG2 w0.152: v1(52.38,33.46) 53.21,32.63 JMP36.1
  BOTTOM w0.254: R556.2 v1(52.38,33.46)
ELF: length 6.6
  TOP w0.254: U100.41 18.91,147.79 18.97,147.85 18.97,149.3 18.8,149.48 R703.1 18.86,149.99 19.43,150.56 19.43,151.89 19.74,152.2 C683.1
ELF_RC: length 1
  TOP w0.254: R703.2 C682.1
EXT_I2C_INT1: length 68.8
  L3_SIG2 w0.152: JMP102.7 28.2,19.69 40.26,19.69 43.11,16.83 48.96,16.83 49.15,17.02 54.53,17.02 58.52,21.01 58.52,28.45 69.67,39.6 77.7,39.6 v1(78.61,40.51)
EXT_I2C_INT2: length 72.5
  L3_SIG2 w0.152: v1(76.96,40.51) 76.33,41.15 69.93,41.15 57.61,28.82 57.61,22.1 57.15,21.64 57.15,21.59 54.61,19.05 49.53,19.05 49.01,18.53 42.89,18.53 39.96,21.47 36.75,21.47 36.2,20.91 24.34,20.91 JMP102.11
EXT_I2C_RESET1: length 73.7
  L3_SIG2 w0.152: JMP102.5 29.59,16.51 39.99,16.51 42.78,13.72 49.4,13.72 49.78,13.34 55.52,13.34 60.07,17.89 60.07,27.69 70.48,38.1 81.15,38.1 v1(83.57,40.51)
EXT_I2C_RESET2: length 78.2
  L3_SIG2 w0.152: JMP102.9 26.11,20.14 40.59,20.14 42.65,18.08 49.97,18.08 50.3,18.41 55.28,18.41 58.06,21.2 58.06,28.64 69.48,40.06 77.15,40.06 78.5,41.4 84.45,41.4 v1(85.34,40.51)
EXT_I2C_SCL: length 65.4
  L3_SIG2 w0.152: v1(81.92,40.51) 80.01,38.61 70.1,38.61 59.44,27.94 59.44,19.75 53.87,14.18 42.97,14.18 39.62,17.53 JMP102.1
EXT_I2C_SDA: length 66
  L3_SIG2 w0.152: JMP102.3 32.13,18.54 39.5,18.54 42.93,15.11 53.45,15.11 58.98,20.64 58.98,28.24 69.85,39.12 78.92,39.12 79.96,40.16 79.96,40.21 v1(80.26,40.51)
EXT_SPI_CLK/PIN4: length 1.9
  BOTTOM w0.254: R763.1 JMP104.9
EXT_SPI_LE1/PIN3: length 1.9
  BOTTOM w0.254: R762.1 JMP104.7
EXT_SPI_LE2: length 1.9
  BOTTOM w0.254: R764.1 JMP104.11
EXT_SPI_MISO/PIN2: length 1.9
  BOTTOM w0.254: R761.1 JMP104.5
EXT_SPI_MOSI/PIN1: length 1.9
  BOTTOM w0.254: R760.1 JMP104.3
EXT_STATUS1/PIN0: length 1.9
  BOTTOM w0.254: R759.1 JMP104.1
GPI1: length 7.2
  TOP w0.254: U64.16 107.06,20.95 106.91,21.1 U42.12
GPI1_LS: length 3
  TOP w0.254: U64.5 117.37,20.95 117.5,20.83 v1(117.98,20.83)
GPIO: length 156.6
  TOP w0.254: v1(113.28,10.16) SW11.13
  L3_SIG2 w0.152: v2(42.09,76.16) 41.8,76.45 41.79,76.45 41.53,76.71 41.53,79.38 42.55,80.39 90.3,80.39 99.44,71.25 117.73,71.25 118.87,70.1 118.87,56.53 115.94,53.59 112.27,53.59 108.58,49.91 108.58,40.13 109.73,38.99 109.73,35.05 108.71,34.04 108.71,27.04 110.97,24.78 110.97,16.54 113.79,13.72 113.79,10.67 v1(113.28,10.16)
GPO0_LS: length 8.9
  TOP w0.254: v1(85.85,13.34) 84.84,14.35 84.84,20.1 84.36,20.57 U41.6
GPO1_LS: length 8.5
  TOP w0.254: v1(79.88,13.46) 81.15,14.73 81.15,18.82 82.25,19.92 U41.7
HSRXAN: length 49.4
  TOP w0.114: J73.12 38.05,31.53 38.36,31.83 41.31,31.83 42.84,33.36 42.84,55.77 34.73,63.87 34.73,66.79 36.53,68.58 39.67,68.58 U1.A12
HSRXAP: length 49.4
  TOP w0.114: U1.B12 39.7,68.77 36.45,68.77 34.54,66.87 34.54,63.79 42.65,55.69 42.65,33.44 41.23,32.02 38.36,32.02 38.05,32.33 J73.13
HSRXBN: length 43.2
  TOP w0.254: U1.G12 38.72,74.16 37.64,73.07 33.07,73.07 23.57,63.58 arc(23.03,63.35) 22.49,63.58 22.4,63.68 arc(21.32,63.68) 21.32,62.6 21.42,62.5 arc(21.42,61.42) 20.34,61.42 20.24,61.52 arc(19.16,61.52) 19.16,60.44 19.26,60.34 arc(19.48,59.81) 19.26,59.27 15.11,55.12 C249.1
HSRXBN_SMA: length 7.6
  TOP w0.254: J8.1 C249.2
HSRXBP: length 43.2
  TOP w0.254: C247.1 11.75,70.36 arc(12.29,70.58) 12.51,71.12 12.51,71.9 arc(13.27,72.66) 14.04,71.9 14.04,71.12 arc(14.8,70.36) 15.56,71.12 15.56,71.9 arc(16.32,72.66) 17.08,71.9 17.08,71.12 arc(17.85,70.36) 18.61,71.12 18.61,71.9 arc(19.37,72.66) 20.13,71.9 20.13,71.12 arc(20.36,70.58) 20.89,70.36 20.94,70.31 22.69,70.31 27.54,75.16 U1.H12
HSRXBP_SMA: length 7.6
  TOP w0.254: J7.1 C247.2
HSTXAN: length 48.7
  TOP w0.114: J73.19 38.06,37.13 38.36,36.82 40.02,36.82 41.2,38 41.2,53.67 31.51,63.36 31.51,67.58 35.69,71.75 39.69,71.75 U1.E12
HSTXAP: length 48.7
  TOP w0.114: J73.18 38.05,36.33 38.35,36.63 40.1,36.63 41.39,37.92 41.39,53.75 31.7,63.44 31.7,67.5 35.77,71.56 39.69,71.56 U1.D12
HSTXBN: length 43.2
  TOP w0.254: U1.L12 38.81,78.16 36.96,80.01 27.69,80.01 13.72,93.98 13.72,98.32 11.19,100.84 R582.1 8.8,100.84
HSTXBN_SMA: length 7.6
  TOP w0.254: R582.2 J6.1
HSTXBP: length 43.2
  TOP w0.254: U1.K12 24.69,77.16 21.37,80.49 arc(20.83,80.71) 20.29,80.49 19.41,79.61 arc(18.33,79.61) 18.33,80.69 19.21,81.57 arc(19.21,82.64) 18.13,82.64 17.26,81.77 arc(16.18,81.77) 16.18,82.84 17.05,83.72 arc(17.28,84.26) 17.05,84.8 16.26,85.6 R581.1 8.8,85.6
HSTXBP_SMA: length 7.6
  TOP w0.254: J5.1 R581.2
I2C_CLK_PDN: length 131.2
  TOP w0.254: U42.24 98.32,24.36 98.04,24.64 v1(97.66,24.64)
  L14_SIG3 w0.152: v1(55.92,119.36) 55.31,118.75 55.31,111.19 63.56,102.93 63.56,61.02 71.59,53 77.3,53 86.07,44.23 86.07,40.68 87.88,38.86 95,38.86 101.47,32.38 101.98,32.38 104.27,30.1 104.27,25.27 103.12,24.13 101.35,24.13 100.84,24.64 v1(97.66,24.64)
I2C_DIS_FET: length 35.4
  TOP w0.254: U42.8 101.82,18.87 102.28,18.41 v1(102.87,18.41)
  L14_SIG3 w0.152: v1(102.87,18.41) 105.54,18.41 113.67,26.54 116.59,26.54 119.51,23.62 119.51,14.59 121.73,12.37 v1(121.73,11.73)
I2C_DIS_FETG: length 1.3
  TOP w0.254: Q100.1 R632.2
I2C_GPIO_ADDR: length 35.5
  TOP w0.254: U42.26 97.41,22.6 v1(96.52,23.5) ; SW11.19 v1(117.09,9.62)
  L14_SIG3 w0.152: v1(117.09,9.62) 117.09,10.25 115.53,11.81 104.78,11.81 104.52,11.56 102.74,11.56 102.11,12.19 102.11,17.27 100.84,18.54 100.84,22.23 99.91,23.15 96.86,23.15 v1(96.52,23.5)
  BOTTOM w0.254: v1(96.52,23.5) R648.2
I2C_GPIO_INT: length 29.4
  TOP w0.254: 95.81,19.54 97.15,19.54 97.21,19.6 U42.32 ; 95.81,19.54 95.74,19.54 95.12,18.92 94.23,18.92 93.34,19.81 93.34,20.57 92.71,21.21 92.71,24.26 91.59,25.37 86.83,25.37 v1(78.61,33.59) ; 95.81,19.54 v1(95.81,19.55)
  BOTTOM w0.254: R650.2 v1(78.61,33.59)
I2C_GPIO_RESET: length 23.3
  TOP w0.254: v1(85.34,33.59) 85.34,31.24 88.39,28.19 94.36,28.19 95.81,26.75 v1(95.81,22.1) 96.31,21.6 U42.28
  BOTTOM w0.254: R510.2 v1(85.34,33.59) ; v1(95.81,22.1) R472.2
I2C_GPIO_SCL: length 23.2
  TOP w0.254: U42.29 95.93,21.1 v1(95.81,21.22) 95.15,21.88 95.15,25.63 93.34,27.43 88.07,27.43 v1(81.92,33.59)
I2C_GPIO_SDA: length 25
  TOP w0.254: U42.30 97.21,20.6 97.15,20.66 96.08,20.66 v1(95.81,20.39) 94.82,20.39 93.34,21.86 93.34,25.02 92.2,26.16 88.9,26.16 88.14,26.92 86.93,26.92 v1(80.26,33.59)
I2C_INT2_SOURCE: length 10.4
  BOTTOM w0.254: R650.1 76.95,39.12 76.86,39.21 ; 76.86,39.21 R656.2 77.06,39.21 77.85,40 77.85,41.02 76.96,41.91 R664.2 ; 76.86,39.21 R658.2
I2C_INT_SOURCE: length 8.6
  BOTTOM w0.254: R654.2 78.71,39.21 ; 78.71,39.21 78.71,35.34 78.61,35.24 R511.1 ; 78.71,39.21 79.5,40 79.5,41.02 78.61,41.91 R662.2
I2C_LOSA: length 4.4
  TOP w0.254: v1(90.55,23.11) 89.96,22.52 U41.18
  BOTTOM w0.254: R621.1 v1(90.55,23.11)
I2C_LOSA/MDIO_C_RLY: length 15.5
  TOP w0.254: v1(97.66,18.41) 97.92,18.41 98.32,18.82 U42.1
  L14_SIG3 w0.152: v1(97.66,18.41) 97.18,18.41 96.77,18.01 93.35,18.01 91.92,19.43 91.92,20.99 91.44,21.48 91.44,24.51 90.55,25.4 v1(90.55,26.8)
I2C_LOSA_LS: length 24.6
  TOP w0.254: v1(100.71,13.34) 98.68,15.37 87.5,15.37 86.61,16.26 86.61,21.97 86.06,22.52 U41.3
I2C_LOSB: length 5.9
  TOP w0.254: U41.17 90.58,21.87 v1(90.81,22.1)
  BOTTOM w0.254: R622.1 91.69,22.99 v1(90.81,22.1)
I2C_LOSB/MDIO_B_RLY: length 16.6
  TOP w0.254: U42.2 98.82,18.43 v1(98.17,17.78)
  L14_SIG3 w0.152: v1(98.17,17.78) 98.17,18.8 97.92,19.05 97.17,19.05 96.58,18.47 93.54,18.47 92.38,19.62 92.38,24.97 91.69,25.65 v1(91.69,26.8)
I2C_LOSB_LS: length 21.7
  TOP w0.254: v1(98.17,13.34) 96.9,14.61 87.25,14.61 86.11,15.75 86.11,21.34 85.57,21.87 U41.4
I2C_LS0_EN: length 14.9
  TOP w0.254: 121.67,19.68 121.6,19.68 120.78,20.51 120.78,23.18 121.09,23.5 R627.1 121.67,24 122.17,24.51 122.17,25.15 121.79,25.53 R629.1 121.16,24.96 120.41,24.21 U64.10
I2C_LS1_EN: length 64.5
  TOP w0.254: U41.10 v1(83.31,16.39) ; R630.1 122.17,26.67 123.06,25.78 R628.1 123.63,23.5 123.95,23.18 123.95,20.51 123.13,19.68 v1(123.06,19.68)
  L3_SIG2 w0.152: v1(123.06,19.68) 122.1,18.72 122.1,18.36 119.23,15.49 v1(117.73,15.49)
  L14_SIG3 w0.152: v1(83.31,16.39) 83.31,15.12 89.66,8.76 93.47,8.76 95.38,6.86 102.23,6.86 103.25,7.87 116.08,7.87 117.73,9.53 v1(117.73,15.49)
I2C_LS_EN: length 24.3
  TOP w0.254: v1(116.46,25.53) R631.2 R633.1 117.35,26.73 118.05,27.43 119.32,27.43 120.02,26.73 R630.2 R629.2
  L14_SIG3 w0.152: v1(116.46,25.53) 115.95,26.04 114.05,26.04 JMP100.1
I2C_MAIN_RESET: length 116.5
  TOP w0.254: U42.9 103.59,19.6 v1(103.95,19.24)
  L3_SIG2 w0.152: v1(81.41,91.19) 103.45,91.19 103.52,91.12 v1(103.95,91.12)
  L14_SIG3 w0.152: v1(81.41,91.19) 81.41,98.3 79.88,99.82 79.88,108.08 v1(81.28,109.47) ; v1(103.95,19.24) 103.95,24.31 104.72,25.08 104.72,57.86 103.71,58.88 103.71,68.12 103.95,68.37 v1(103.95,91.12)
I2C_PDTRXA_N: length 7.3
  TOP w0.254: U42.10 105.5,20.1 105.95,19.65 U64.18
I2C_PDTRXA_N_LS: length 3.5
  TOP w0.254: v1(117.98,18.29) 116.62,19.65 U64.3
I2C_PDTRXB_N: length 7.2
  TOP w0.254: U42.11 106.27,20.6 106.57,20.3 U64.17
I2C_PDTRXB_N_LS: length 3.2
  TOP w0.254: U64.4 117.24,20.3 v1(117.98,19.56)
I2C_PRBS_PASS: length 14.6
  TOP w0.254: U42.3 99.32,17.79 98.68,17.14 93.92,17.14 92.71,18.35 92.71,20.07 91.55,21.22 U41.16
I2C_PRBS_PASS_LS: length 18.6
  TOP w0.254: U41.5 84.82,21.22 85.47,20.57 85.47,15.49 86.87,14.1 94.87,14.1 v1(95.63,13.34)
I2C_PRBSEN: length 7.2
  TOP w0.254: U64.14 107.04,22.26 106.88,22.1 102.93,22.1 102.93,22.1 U42.14
I2C_PRBSEN_LS: length 3.4
  TOP w0.254: U64.7 116.87,22.26 v1(117.98,23.37)
I2C_REF_SEL: length 217.6
  TOP w0.254: U42.19 100.82,25.27 v1(101.46,25.91)
  L14_SIG3 w0.152: v1(1.4,167.87) 2.02,167.87 3.46,169.3 12.99,169.3 15.42,166.88 15.42,156.39 14.81,155.78 14.81,151.33 15.85,150.29 27.53,150.29 35.31,142.52 35.31,123.44 41.02,117.73 50.16,117.73 53.09,114.81 53.09,109.98 61.98,101.09 61.98,60.33 70.87,51.44 75.56,51.44 82.68,44.32 82.68,35.94 84.45,34.16 96.01,34.16 97.66,32.51 97.66,31.88 101.47,28.07 101.47,26.35 101.46,26.34 v1(101.46,25.91)
  BOTTOM w0.254: R720.1 v1(1.4,167.87)
I2C_RESET2_SOURCE: length 10.1
  BOTTOM w0.254: R655.2 85.44,39.21 ; 85.44,39.21 85.44,35.34 85.34,35.24 R649.1 ; 85.44,39.21 85.57,39.21 ; 85.57,39.21 R657.2 ; 85.57,39.21 85.57,39.34 86.05,39.82 86.05,40.97 85.34,41.67 R663.2
I2C_RESET/PWR: length 139.4
  TOP w0.254: v1(98.17,25.4) 98.82,24.75 U42.23
  L14_SIG3 w0.152: v1(98.17,25.4) 98.17,26.8 96.72,28.24 80.59,28.24 79.25,29.59 79.25,44.7 74.55,49.4 69.85,49.4 59.94,59.31 59.94,71.75 59.82,71.88 59.82,99.95 52.96,106.81 51.18,106.81 49.28,108.71 31.5,108.71 30.21,109.99 v1(30.21,110.97)
I2C_RESET_SOURCE: length 8.6
  BOTTOM w0.254: R661.2 83.57,41.91 84.45,41.02 84.45,40 83.67,39.21 ; R653.2 83.67,39.21 ; 83.67,39.21 83.67,35.34 83.57,35.24 R510.1
I2C_SCL_SOURCE: length 8.6
  BOTTOM w0.254: R508.1 81.92,35.24 82.02,35.34 82.02,39.21 ; 82.02,39.21 R651.2 ; 82.02,39.21 82.8,40 82.8,41.02 81.92,41.91 R659.2
I2C_SDA_SOURCE: length 8.7
  BOTTOM w0.254: R509.1 80.26,35.24 80.39,35.37 80.39,39.09 R652.2 80.36,39.21 81.15,40 81.15,41.02 80.26,41.91 R660.2
I2C_SI_MODE0: length 215.9
  TOP w0.254: v1(100.95,26.54) 100.32,25.91 U42.20
  L14_SIG3 w0.152: v1(100.95,26.54) 100.95,27.82 97.41,31.37 97.03,31.37 95.54,32.86 83.6,32.86 81.41,35.05 81.41,44.83 75.31,50.93 70.61,50.93 61.47,60.07 61.47,100.93 52.12,110.28 52.12,115.01 49.91,117.22 40.77,117.22 33.83,124.16 33.83,143.34 27.57,149.61 19.67,149.61 19.5,149.43 15.79,149.43 14.35,150.86 14.35,157.35 14.77,157.77 14.77,166.88 12.8,168.85 4.27,168.85 3.29,167.87 v1(2.67,167.87)
  BOTTOM w0.254: R721.1 v1(2.67,167.87)
I2C_SI_MODE1: length 213
  TOP w0.254: U42.21 99.82,25.91 v1(99.19,26.54)
  L14_SIG3 w0.152: v1(3.94,167.87) 4.46,168.39 12.61,168.39 13.84,167.16 13.84,150.73 15.6,148.97 19.68,148.97 19.86,149.15 27.38,149.15 33.38,143.15 33.38,123.86 40.48,116.76 49.61,116.76 51.56,114.81 51.56,110.1 60.96,100.7 60.96,59.82 70.36,50.42 75.06,50.42 80.77,44.7 80.77,33.78 82.17,32.38 94.74,32.38 99.19,27.94 v1(99.19,26.54)
  BOTTOM w0.254: R722.1 v1(3.94,167.87)
I2C_STATUS0: length 185.8
  TOP w0.254: U42.17 101.82,24.36 102.1,24.64 v1(102.48,24.64) ; R712.2 v1(15.24,151.51)
  L14_SIG3 w0.152: v1(15.24,151.51) 16.85,151.51 17.34,151.99 27.46,151.99 36.22,143.23 36.22,123.95 41.43,118.75 50.8,118.75 54.1,115.44 54.1,110.49 62.99,101.6 62.99,60.83 71.37,52.45 76.45,52.45 84.71,44.2 84.71,39.75 86.11,38.35 93.65,38.35 96.32,35.69 97.28,35.69 98.81,34.16 98.81,33.66 102.48,29.98 v1(102.48,24.64)
